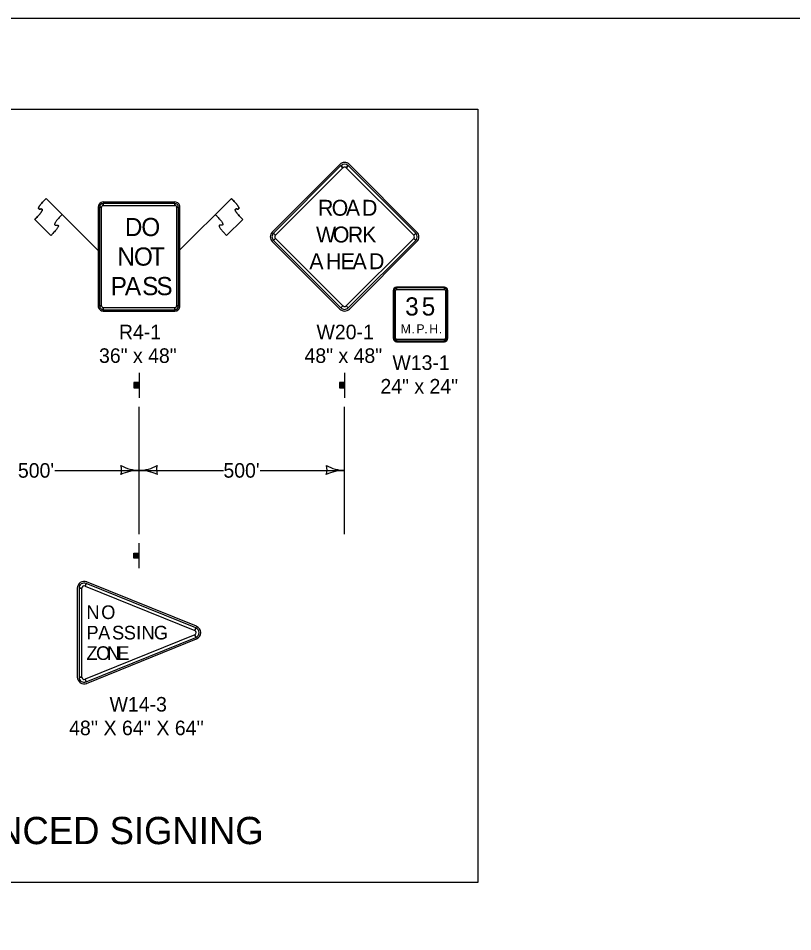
# Model space of a CAD drawing. Extents: x -2134934 to -2122394, y -2140205 to -2137036.
# Drawn here: x -2124814 to -2123962, y -2138041 to -2137036 of the extents above; entities that cross this region are included whole.
import ezdxf

# ---------------------------------------------------------------- set-up
doc = ezdxf.new("R2010")
doc.units = 0
for name, color, linetype in [('Barrier', 7, 'Continuous'), ('BridgeSuperStructureExisting', 7, 'Continuous'), ('Default', 7, 'Continuous'), ('TC_Barrier', 7, 'Continuous')]:
    doc.layers.add(name, color=color, linetype=linetype)

msp = doc.modelspace()

# ---------------------------------------------------------------- linework, layer by layer
at = {"layer": 'Barrier'}
for p, q in [((-2124460.1, -2137196.8), (-2124534.4, -2137271.1)), ((-2124458.8, -2137198.1), (-2124456.6, -2137200.4)), ((-2124453.1, -2137200.4), (-2124450.9, -2137198.1)), ((-2124375.3, -2137271.1), (-2124449.5, -2137196.8)), ((-2124725.9, -2137291.6), (-2124783.2, -2137234.3)), ((-2124783.2, -2137234.3), (-2124765.5, -2137252)), ((-2124641.5, -2137238.1), (-2124720.2, -2137238.1)), ((-2124636.6, -2137291.6), (-2124579.3, -2137234.3)), ((-2124579.3, -2137234.3), (-2124596.9, -2137252)), ((-2124725.9, -2137243.7), (-2124725.9, -2137352.5)), ((-2124724.3, -2137243.7), (-2124722.1, -2137243.7)), ((-2124720.2, -2137241.9), (-2124720.2, -2137239.7)), ((-2124641.5, -2137239.7), (-2124641.5, -2137241.9)), ((-2124639.6, -2137243.7), (-2124637.4, -2137243.7)), ((-2124635.9, -2137352.5), (-2124635.9, -2137243.7)), ((-2124777.9, -2137275), (-2124795.6, -2137257.3)), ((-2124584.6, -2137275), (-2124566.9, -2137257.3)), ((-2124530.9, -2137274.6), (-2124533.1, -2137272.4)), ((-2124533.1, -2137280.3), (-2124530.9, -2137278.1)), ((-2124376.6, -2137272.4), (-2124378.8, -2137274.6)), ((-2124378.8, -2137278.1), (-2124376.6, -2137280.3)), ((-2124534.4, -2137281.7), (-2124460.1, -2137355.9)), ((-2124449.5, -2137355.9), (-2124375.3, -2137281.7)), ((-2124401.3, -2137335.5), (-2124401.3, -2137388)), ((-2124400.4, -2137335.5), (-2124398.8, -2137335.5)), ((-2124345.1, -2137331.8), (-2124397.6, -2137331.8)), ((-2124397.6, -2137334.3), (-2124397.6, -2137332.7)), ((-2124345.1, -2137332.7), (-2124345.1, -2137334.3)), ((-2124343.8, -2137335.5), (-2124342.3, -2137335.5)), ((-2124341.3, -2137388), (-2124341.3, -2137335.5)), ((-2124722.1, -2137352.5), (-2124724.3, -2137352.5)), ((-2124720.2, -2137356.6), (-2124720.2, -2137354.4)), ((-2124720.2, -2137358.1), (-2124641.5, -2137358.1)), ((-2124641.5, -2137354.4), (-2124641.5, -2137356.6)), ((-2124637.4, -2137352.5), (-2124639.6, -2137352.5)), ((-2124456.6, -2137352.4), (-2124458.8, -2137354.6)), ((-2124450.9, -2137354.6), (-2124453.1, -2137352.4)), ((-2124398.8, -2137388), (-2124400.4, -2137388)), ((-2124397.6, -2137390.8), (-2124397.6, -2137389.3)), ((-2124345.1, -2137389.3), (-2124345.1, -2137390.8)), ((-2124342.3, -2137388), (-2124343.8, -2137388)), ((-2124397.6, -2137391.8), (-2124345.1, -2137391.8)), ((-2124740.3, -2137660.7), (-2124739.2, -2137657.8)), ((-2124617.6, -2137704.9), (-2124738.5, -2137656.1)), ((-2124748.8, -2137663), (-2124748.8, -2137760.8)), ((-2124746.9, -2137663), (-2124743.8, -2137663)), ((-2124618.4, -2137706.7), (-2124619.5, -2137709.6)), ((-2124738.5, -2137767.7), (-2124617.6, -2137718.8)), ((-2124619.5, -2137714.2), (-2124618.4, -2137717.1)), ((-2124743.8, -2137760.8), (-2124746.9, -2137760.8)), ((-2124739.2, -2137766), (-2124740.3, -2137763.1))]:
    msp.add_line(p, q, dxfattribs=at)
for points in [[(-2125429.5, -2137135.9), (-2124308.2, -2137135.9), (-2124308.2, -2137986.6), (-2125429.5, -2137986.6)], [(-2124458.8, -2137198.1), (-2124533.1, -2137272.4), (-2124530.9, -2137274.6), (-2124456.6, -2137200.4), (-2124458.8, -2137198.1)], [(-2124376.6, -2137272.4), (-2124450.9, -2137198.1), (-2124453.1, -2137200.4), (-2124378.8, -2137274.6), (-2124376.6, -2137272.4)], [(-2124724.3, -2137243.7), (-2124724.3, -2137352.5), (-2124722.1, -2137352.5), (-2124722.1, -2137243.7), (-2124724.3, -2137243.7)], [(-2124641.5, -2137239.7), (-2124720.2, -2137239.7), (-2124720.2, -2137241.9), (-2124641.5, -2137241.9), (-2124641.5, -2137239.7)], [(-2124637.4, -2137352.5), (-2124637.4, -2137243.7), (-2124639.6, -2137243.7), (-2124639.6, -2137352.5), (-2124637.4, -2137352.5)], [(-2124533.1, -2137280.3), (-2124458.8, -2137354.6), (-2124456.6, -2137352.4), (-2124530.9, -2137278.1), (-2124533.1, -2137280.3)], [(-2124450.9, -2137354.6), (-2124376.6, -2137280.3), (-2124378.8, -2137278.1), (-2124453.1, -2137352.4), (-2124450.9, -2137354.6)], [(-2124400.4, -2137335.5), (-2124400.4, -2137388), (-2124398.8, -2137388), (-2124398.8, -2137335.5), (-2124400.4, -2137335.5)], [(-2124345.1, -2137332.7), (-2124397.6, -2137332.7), (-2124397.6, -2137334.3), (-2124345.1, -2137334.3), (-2124345.1, -2137332.7)], [(-2124342.3, -2137388), (-2124342.3, -2137335.5), (-2124343.8, -2137335.5), (-2124343.8, -2137388), (-2124342.3, -2137388)], [(-2124720.2, -2137356.6), (-2124641.5, -2137356.6), (-2124641.5, -2137354.4), (-2124720.2, -2137354.4), (-2124720.2, -2137356.6)], [(-2124397.6, -2137390.8), (-2124345.1, -2137390.8), (-2124345.1, -2137389.3), (-2124397.6, -2137389.3), (-2124397.6, -2137390.8)], [(-2124618.4, -2137706.7), (-2124739.2, -2137657.8), (-2124740.3, -2137660.7), (-2124619.5, -2137709.6), (-2124618.4, -2137706.7)], [(-2124746.9, -2137663), (-2124746.9, -2137760.8), (-2124743.8, -2137760.8), (-2124743.8, -2137663), (-2124746.9, -2137663)], [(-2124739.2, -2137766), (-2124618.4, -2137717.1), (-2124619.5, -2137714.2), (-2124740.3, -2137763.1), (-2124739.2, -2137766)]]:
    msp.add_lwpolyline(points, close=True, dxfattribs=at)
for centre, radius, start, end in [((-2124454.8, -2137202.1), 7.5, 45, 134.9997), ((-2124454.8, -2137202.1), 5.62, 45, 134.9997), ((-2124454.8, -2137202.1), 2.5, 45, 134.9997), ((-2124720.2, -2137243.7), 5.62, 90.0002, 179.9998), ((-2124641.5, -2137243.7), 5.62, 0, 90.0002), ((-2124720.2, -2137243.7), 4.06, 90.0002, 179.9998), ((-2124720.2, -2137243.7), 1.87, 90.0002, 179.9998), ((-2124641.5, -2137243.7), 4.06, 0, 90.0002), ((-2124641.5, -2137243.7), 1.87, 0, 90.0002), ((-2124529.1, -2137276.4), 7.5, 134.9997, 225), ((-2124529.1, -2137276.4), 5.62, 134.9997, 225), ((-2124529.1, -2137276.4), 2.5, 134.9997, 225), ((-2124380.6, -2137276.4), 2.5, 315.0002, 44.9998), ((-2124380.6, -2137276.4), 5.62, 315.0002, 44.9998), ((-2124380.6, -2137276.4), 7.5, 315.0002, 44.9998), ((-2124397.6, -2137335.5), 3.75, 90.0002, 179.9998), ((-2124397.6, -2137335.5), 2.81, 90.0002, 179.9998), ((-2124397.6, -2137335.5), 1.25, 90.0002, 179.9998), ((-2124345.1, -2137335.5), 3.75, 0, 90.0002), ((-2124345.1, -2137335.5), 2.81, 0, 90.0002), ((-2124345.1, -2137335.5), 1.25, 0, 90.0002), ((-2124720.2, -2137352.5), 5.62, 179.9998, 270.0001), ((-2124720.2, -2137352.5), 4.06, 179.9998, 270.0001), ((-2124720.2, -2137352.5), 1.87, 179.9998, 270.0001), ((-2124641.5, -2137352.5), 5.62, 270.0001, 0.0003), ((-2124641.5, -2137352.5), 4.06, 270.0001, 0.0003), ((-2124641.5, -2137352.5), 1.87, 270.0001, 0.0003), ((-2124454.8, -2137350.6), 7.5, 225, 315.0002), ((-2124454.8, -2137350.6), 5.62, 225, 315.0002), ((-2124454.8, -2137350.6), 2.5, 225, 315.0002), ((-2124397.6, -2137388), 3.75, 179.9998, 270.0001), ((-2124397.6, -2137388), 2.81, 179.9998, 270.0001), ((-2124397.6, -2137388), 1.25, 179.9998, 270.0001), ((-2124345.1, -2137388), 3.75, 270.0001, 0.0003), ((-2124345.1, -2137388), 2.81, 270.0001, 0.0003), ((-2124345.1, -2137388), 1.25, 270.0001, 0.0003), ((-2124741.3, -2137663), 7.5, 67.9757, 179.9998), ((-2124741.3, -2137663), 5.62, 67.9757, 179.9998), ((-2124741.3, -2137663), 2.5, 67.9757, 179.9998), ((-2124620.5, -2137711.9), 2.5, 292.0246, 67.9754), ((-2124620.5, -2137711.9), 5.62, 292.0246, 67.9754), ((-2124620.5, -2137711.9), 7.5, 292.0246, 67.976), ((-2124741.3, -2137760.8), 7.5, 179.9998, 292.0246), ((-2124741.3, -2137760.8), 5.62, 179.9998, 292.0246), ((-2124741.3, -2137760.8), 2.5, 179.9998, 292.0246)]:
    msp.add_arc(centre, radius, start, end, dxfattribs=at)
for points in [[(-2124795.6, -2137257.3), (-2124783.2, -2137244.9), (-2124795.6, -2137246.7), (-2124783.2, -2137234.3)], [(-2124566.9, -2137257.3), (-2124579.3, -2137244.9), (-2124566.9, -2137246.7), (-2124579.3, -2137234.3)], [(-2124765.5, -2137252), (-2124777.9, -2137264.4), (-2124765.5, -2137262.6), (-2124777.9, -2137275)], [(-2124596.9, -2137252), (-2124584.6, -2137264.4), (-2124596.9, -2137262.6), (-2124584.6, -2137275)]]:
    msp.add_open_spline(points, degree=2, dxfattribs=at)
at = {"layer": 'BridgeSuperStructureExisting'}
for p, q in [((-2124680.9, -2137425.9), (-2124680.9, -2137453.4)), ((-2124454.8, -2137425.9), (-2124454.8, -2137453.4)), ((-2124686.2, -2137436.8), (-2124686.2, -2137442.4)), ((-2124685.9, -2137442.4), (-2124685.9, -2137436.8)), ((-2124685.7, -2137436.8), (-2124685.7, -2137442.4)), ((-2124685.3, -2137442.4), (-2124685.3, -2137436.8)), ((-2124685.1, -2137436.8), (-2124685.1, -2137442.4)), ((-2124684.7, -2137442.4), (-2124684.7, -2137436.8)), ((-2124684.5, -2137436.8), (-2124684.5, -2137442.4)), ((-2124684, -2137442.4), (-2124684, -2137436.8)), ((-2124683.7, -2137436.8), (-2124683.7, -2137442.4)), ((-2124683.3, -2137442.4), (-2124683.3, -2137436.8)), ((-2124683.1, -2137436.8), (-2124683.1, -2137442.4)), ((-2124682.9, -2137442.4), (-2124682.9, -2137436.8)), ((-2124682.5, -2137436.8), (-2124682.5, -2137442.4)), ((-2124682.3, -2137442.4), (-2124682.3, -2137436.8)), ((-2124682.1, -2137436.8), (-2124682.1, -2137442.4)), ((-2124681.8, -2137442.4), (-2124681.8, -2137436.8)), ((-2124681.6, -2137436.8), (-2124681.6, -2137442.4)), ((-2124681.3, -2137442.4), (-2124681.3, -2137436.8)), ((-2124460.2, -2137436.8), (-2124460.2, -2137442.4)), ((-2124459.8, -2137442.4), (-2124459.8, -2137436.8)), ((-2124459.6, -2137436.8), (-2124459.6, -2137442.4)), ((-2124459.3, -2137442.4), (-2124459.3, -2137436.8)), ((-2124459.1, -2137436.8), (-2124459.1, -2137442.4)), ((-2124458.7, -2137442.4), (-2124458.6, -2137436.8)), ((-2124458.4, -2137436.8), (-2124458.4, -2137442.4)), ((-2124458, -2137442.4), (-2124458, -2137436.8)), ((-2124457.6, -2137436.8), (-2124457.6, -2137442.4)), ((-2124457.3, -2137442.4), (-2124457.3, -2137436.8)), ((-2124457.1, -2137436.8), (-2124457.1, -2137442.4)), ((-2124456.8, -2137442.4), (-2124456.8, -2137436.8)), ((-2124456.5, -2137436.8), (-2124456.5, -2137442.4)), ((-2124456.3, -2137442.4), (-2124456.3, -2137436.8)), ((-2124456.1, -2137436.8), (-2124456.1, -2137442.4)), ((-2124455.8, -2137442.4), (-2124455.8, -2137436.8)), ((-2124455.5, -2137436.8), (-2124455.5, -2137442.4)), ((-2124455.2, -2137442.4), (-2124455.2, -2137436.8)), ((-2124680.9, -2137603.4), (-2124680.9, -2137463.4)), ((-2124454.8, -2137603.4), (-2124454.8, -2137463.4)), ((-2124773.6, -2137533.4), (-2124680.9, -2137533.4)), ((-2124680.9, -2137533.4), (-2124588.1, -2137533.4)), ((-2124547.6, -2137533.4), (-2124454.8, -2137533.4)), ((-2124680.9, -2137640.9), (-2124680.9, -2137613.4)), ((-2124686.2, -2137630.1), (-2124686.2, -2137624.5)), ((-2124685.9, -2137624.5), (-2124685.9, -2137630.1)), ((-2124685.7, -2137630.1), (-2124685.7, -2137624.5)), ((-2124685.3, -2137624.5), (-2124685.3, -2137630.1)), ((-2124685.1, -2137630.1), (-2124685.1, -2137624.5)), ((-2124684.7, -2137624.5), (-2124684.7, -2137630.1)), ((-2124684.5, -2137630.1), (-2124684.5, -2137624.5)), ((-2124684, -2137624.5), (-2124684, -2137630.1)), ((-2124683.7, -2137630.1), (-2124683.7, -2137624.5)), ((-2124683.3, -2137624.5), (-2124683.3, -2137630.1)), ((-2124683.1, -2137630.1), (-2124683.1, -2137624.5)), ((-2124682.9, -2137624.5), (-2124682.9, -2137630.1)), ((-2124682.5, -2137630.1), (-2124682.5, -2137624.5)), ((-2124682.3, -2137624.5), (-2124682.3, -2137630.1)), ((-2124682.1, -2137630.1), (-2124682.1, -2137624.5)), ((-2124681.8, -2137624.5), (-2124681.8, -2137630.1)), ((-2124681.6, -2137630.1), (-2124681.6, -2137624.5)), ((-2124681.3, -2137624.5), (-2124681.3, -2137630.1))]:
    msp.add_line(p, q, dxfattribs=at)
for points in [[(-2124681, -2137442.4), (-2124681, -2137436.8), (-2124686.6, -2137436.8), (-2124686.6, -2137442.4)], [(-2124454.9, -2137442.4), (-2124454.9, -2137436.8), (-2124460.6, -2137436.8), (-2124460.6, -2137442.4)], [(-2124681, -2137624.5), (-2124681, -2137630.1), (-2124686.6, -2137630.1), (-2124686.6, -2137624.5)]]:
    msp.add_lwpolyline(points, close=True, dxfattribs=at)
for centre, radius, start, end in [((-2124716.5, -2137532.8), 16.4, 341.2666, 16.7334), ((-2124680.1, -2137490.9), 42.5, 240.9275, 268.9824), ((-2124681.6, -2137490.9), 42.5, 271.0176, 299.0725), ((-2124645.3, -2137532.8), 16.4, 163.2666, 198.7334), ((-2124490.5, -2137532.8), 16.4, 341.2666, 16.7334), ((-2124454.1, -2137490.9), 42.5, 240.9275, 268.9824), ((-2124681.6, -2137575.9), 42.5, 89.0176, 117.0725), ((-2124680.1, -2137575.9), 42.5, 62.9275, 90.9824), ((-2124455.6, -2137575.9), 42.5, 89.0176, 117.0725)]:
    msp.add_arc(centre, radius, start, end, dxfattribs=at)
at = {"layer": 'Default'}
msp.add_lwpolyline([(-2125529.5, -2137035.9), (-2122394.5, -2137035.9), (-2122394.5, -2139045.9), (-2125529.5, -2139045.9)], close=True, dxfattribs=at)
at = {"layer": 'TC_Barrier'}
for p, q in [((-2124795.6, -2137257.3), (-2124777.9, -2137275)), ((-2124566.9, -2137257.3), (-2124584.6, -2137275))]:
    msp.add_line(p, q, dxfattribs=at)
for points in [[(-2124783.2, -2137234.3), (-2124795.6, -2137246.7), (-2124783.2, -2137244.9), (-2124795.6, -2137257.3)], [(-2124579.3, -2137234.3), (-2124566.9, -2137246.7), (-2124579.3, -2137244.9), (-2124566.9, -2137257.3)], [(-2124765.5, -2137252), (-2124777.9, -2137264.4), (-2124765.5, -2137262.6), (-2124777.9, -2137275)], [(-2124596.9, -2137252), (-2124584.6, -2137264.4), (-2124596.9, -2137262.6), (-2124584.6, -2137275)]]:
    msp.add_open_spline(points, degree=2, dxfattribs=at)

# ---------------------------------------------------------------- texts
at = {"layer": 'Barrier'}
for s, height, p in [('R', 17.5, (-2124484, -2137253.2)), ('O', 17.5, (-2124469, -2137253.2)), ('A', 17.5, (-2124453.4, -2137253.2)), ('D', 17.5, (-2124435.6, -2137253.2)), ('D', 20, (-2124696.5, -2137275.6)), ('O', 20, (-2124678.4, -2137275.6)), ('W', 17.5, (-2124486.3, -2137282.6)), ('O', 17.5, (-2124467.7, -2137282.6)), ('R', 17.5, (-2124451.3, -2137282.6)), ('K', 17.5, (-2124435.4, -2137282.6)), ('N', 20, (-2124704.6, -2137308.1)), ('O', 20, (-2124686.5, -2137308.1)), ('T', 20, (-2124668.7, -2137308.1)), ('A', 17.5, (-2124493.6, -2137312)), ('H', 17.5, (-2124475.4, -2137312)), ('E', 17.5, (-2124459.1, -2137312)), ('A', 17.5, (-2124446.1, -2137312)), ('D', 17.5, (-2124427.9, -2137312)), ('P', 20, (-2124712.1, -2137340.6)), ('A', 20, (-2124696.5, -2137340.6)), ('S', 20, (-2124677.5, -2137340.6)), ('S', 20, (-2124661.8, -2137340.6)), ('3', 20, (-2124388.2, -2137363)), ('5', 20, (-2124370, -2137363)), ('R4-1', 16, (-2124703, -2137389.1)), ('W20-1', 16, (-2124485.7, -2137389.1)), ('M', 10, (-2124393.1, -2137382.7)), ('P', 10, (-2124375.8, -2137382.7)), ('H', 10, (-2124361.7, -2137382.7)), ('.', 10, (-2124381.3, -2137382.7)), ('.', 10, (-2124367.2, -2137382.7)), ('.', 10, (-2124351.2, -2137382.7)), ('36" x 48"', 16, (-2124724.9, -2137415.1)), ('48" x 48"', 16, (-2124498.9, -2137415.1)), ('W13-1', 16, (-2124402.2, -2137422.8)), ('24" x 24"', 16, (-2124415.4, -2137448.8)), ('N', 15, (-2124738.8, -2137696.9)), ('O', 15, (-2124722.5, -2137696.9)), ('P', 15, (-2124738.8, -2137719.4)), ('A', 15, (-2124725.9, -2137719.4)), ('S', 15, (-2124710.6, -2137719.4)), ('S', 15, (-2124697.7, -2137719.4)), ('I', 15, (-2124684.1, -2137719.4)), ('N', 15, (-2124678.2, -2137719.4)), ('G', 15, (-2124664.6, -2137719.4)), ('Z', 15, (-2124738.8, -2137741.9)), ('O', 15, (-2124728.1, -2137741.9)), ('N', 15, (-2124716.2, -2137741.9)), ('E', 15, (-2124704.9, -2137741.9)), ('W14-3', 16, (-2124713.3, -2137798.7)), ("48'' X 64'' X 64''", 16, (-2124757.8, -2137824.7)), ('EXETER AVE ADVANCED SIGNING', 30, (-2125210.4, -2137944.6))]:
    msp.add_text(s, height=height, dxfattribs=at).set_placement(p)
at = {"layer": 'BridgeSuperStructureExisting'}
for p in [(-2124814.1, -2137541.4), (-2124588.1, -2137541.4)]:
    msp.add_text("500'", height=16, dxfattribs=at).set_placement(p)

doc.saveas('drawing.dxf')
